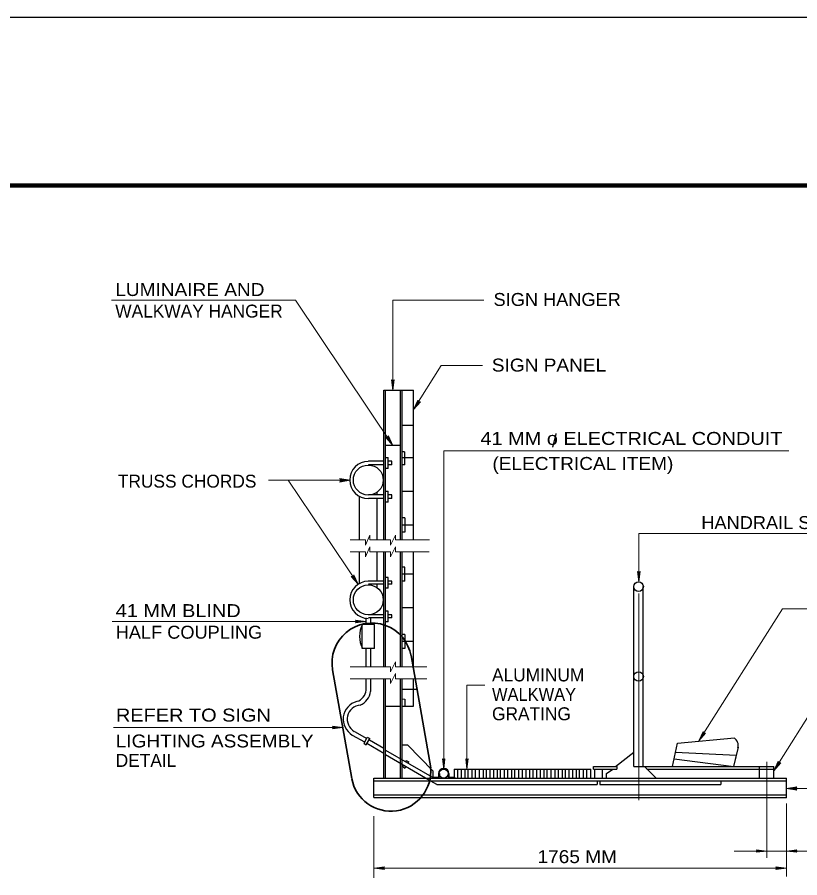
# Model space of a CAD drawing. Extents: x 312601.858 to 312602.699, y 144420.109 to 144420.704.
# Drawn here: x 312602.1557 to 312602.337, y 144420.5041 to 144420.7035 of the extents above; entities that cross this region are included whole.
import ezdxf
from ezdxf.enums import TextEntityAlignment as Align

# ---------------------------------------------------------------- set-up
doc = ezdxf.new("R2010")
doc.units = 0
doc.header["$LTSCALE"] = 0.0012
for name, pattern in [('DOT_DASHED', [7.7, 5, -1.2, 0.3, -1.2]), ('LONG_DASH_SHORT_DASH', [9.9, 6, -1.2, 1.5, -1.2]), ('LONG_DASHED', [7.5, 6, -1.5])]:
    doc.linetypes.add(name, pattern=pattern)
for name, color, linetype, lineweight in [('1', 7, 'Continuous', 25), ('2', 7, 'Continuous', 25), ('39', 7, 'Continuous', 13)]:
    doc.layers.add(name, color=color, linetype=linetype, lineweight=lineweight)

msp = doc.modelspace()

# ---------------------------------------------------------------- hatches: boundary and pattern name
at = {"layer": '39'}
for points in [[(312602.2427, 144420.6193), (312602.243, 144420.6195), (312602.2427, 144420.6171), (312602.2424, 144420.6195)], [(312602.2487, 144420.6144), (312602.2491, 144420.6144), (312602.2475, 144420.6126), (312602.2485, 144420.6148)], [(312602.2415, 144420.6061), (312602.2417, 144420.6065), (312602.2427, 144420.6043), (312602.2411, 144420.6061)], [(312602.2306, 144420.5962), (312602.2304, 144420.5966), (312602.2328, 144420.5962), (312602.2304, 144420.5958)], [(312602.2306, 144420.5962), (312602.2304, 144420.5966), (312602.2328, 144420.5962), (312602.2304, 144420.5958)], [(312602.2997, 144420.5749), (312602.3, 144420.5751), (312602.2997, 144420.5727), (312602.2994, 144420.5751)], [(312602.2997, 144420.5749), (312602.3, 144420.5751), (312602.2997, 144420.5727), (312602.2994, 144420.5751)], [(312602.2335, 144420.5739), (312602.2337, 144420.5743), (312602.2347, 144420.5721), (312602.2331, 144420.5739)], [(312602.2343, 144420.5635), (312602.2341, 144420.5638), (312602.2365, 144420.5635), (312602.2341, 144420.5632)], [(312602.2343, 144420.5635), (312602.2341, 144420.5638), (312602.2365, 144420.5635), (312602.2341, 144420.5632)], [(312602.2289, 144420.5389), (312602.2287, 144420.5392), (312602.2311, 144420.5389), (312602.2287, 144420.5386)], [(312602.2289, 144420.5389), (312602.2287, 144420.5392), (312602.2311, 144420.5389), (312602.2287, 144420.5386)], [(312602.3148, 144420.5376), (312602.3152, 144420.5376), (312602.3136, 144420.5358), (312602.3146, 144420.538)], [(312602.2545, 144420.5315), (312602.2548, 144420.5317), (312602.2545, 144420.5293), (312602.2542, 144420.5317)], [(312602.2599, 144420.5315), (312602.2602, 144420.5317), (312602.2599, 144420.5293), (312602.2596, 144420.5317)], [(312602.2599, 144420.5315), (312602.2602, 144420.5317), (312602.2599, 144420.5293), (312602.2596, 144420.5317)], [(312602.3322, 144420.5307), (312602.3326, 144420.5307), (312602.331, 144420.5289), (312602.332, 144420.5311)], [(312602.3322, 144420.5307), (312602.3326, 144420.5307), (312602.331, 144420.5289), (312602.332, 144420.5311)], [(312602.3361, 144420.5248), (312602.3363, 144420.5244), (312602.3339, 144420.5248), (312602.3363, 144420.5252)], [(312602.3361, 144420.5248), (312602.3363, 144420.5244), (312602.3339, 144420.5248), (312602.3363, 144420.5252)], [(312602.3272, 144420.5103), (312602.327, 144420.5106), (312602.3294, 144420.5103), (312602.327, 144420.51)], [(312602.3272, 144420.5103), (312602.327, 144420.5106), (312602.3294, 144420.5103), (312602.327, 144420.51)], [(312602.3361, 144420.5103), (312602.3363, 144420.51), (312602.3339, 144420.5103), (312602.3363, 144420.5106)], [(312602.3361, 144420.5103), (312602.3363, 144420.51), (312602.3339, 144420.5103), (312602.3363, 144420.5106)], [(312602.2406, 144420.5063), (312602.2408, 144420.506), (312602.2384, 144420.5063), (312602.2408, 144420.5066)], [(312602.2406, 144420.5063), (312602.2408, 144420.506), (312602.2384, 144420.5063), (312602.2408, 144420.5066)], [(312602.3317, 144420.5063), (312602.3315, 144420.5066), (312602.3339, 144420.5063), (312602.3315, 144420.506)]]:
    msp.add_hatch(color=256, dxfattribs=at).paths.add_polyline_path(points)

# ---------------------------------------------------------------- linework, layer by layer
at = {"layer": '1', "lineweight": 13}
for p, q in [((312602.2202, 144420.6379), (312602.1775, 144420.6379)), ((312602.2427, 144420.6043), (312602.2202, 144420.6379)), ((312602.2427, 144420.6171), (312602.2427, 144420.6379)), ((312602.2638, 144420.6379), (312602.2427, 144420.6379)), ((312602.2545, 144420.5293), (312602.2545, 144420.603)), ((312602.3345, 144420.603), (312602.2545, 144420.603)), ((312602.2328, 144420.5962), (312602.2139, 144420.5962)), ((312602.2347, 144420.5721), (312602.2185, 144420.5962)), ((312602.2364, 144420.5812), (312602.2374, 144420.5835)), ((312602.2374, 144420.5824), (312602.2374, 144420.5835)), ((312602.2422, 144420.5812), (312602.2433, 144420.5835)), ((312602.2433, 144420.5824), (312602.2433, 144420.5835)), ((312602.2997, 144420.5839), (312602.3587, 144420.5839)), ((312602.2997, 144420.5727), (312602.2997, 144420.5839)), ((312602.2328, 144420.5824), (312602.2364, 144420.5824)), ((312602.2364, 144420.5812), (312602.2364, 144420.5824)), ((312602.2364, 144420.5785), (312602.2374, 144420.5808)), ((312602.2374, 144420.5796), (312602.2374, 144420.5808)), ((312602.2422, 144420.5812), (312602.2422, 144420.5824)), ((312602.2422, 144420.5785), (312602.2433, 144420.5808)), ((312602.2433, 144420.5824), (312602.2512, 144420.5824)), ((312602.2433, 144420.5796), (312602.2433, 144420.5808)), ((312602.2328, 144420.5796), (312602.2364, 144420.5796)), ((312602.2364, 144420.5785), (312602.2364, 144420.5796)), ((312602.2374, 144420.5796), (312602.2422, 144420.5796)), ((312602.2422, 144420.5785), (312602.2422, 144420.5796)), ((312602.2433, 144420.5796), (312602.2511, 144420.5796)), ((312602.3136, 144420.5358), (312602.333, 144420.5664)), ((312602.333, 144420.5664), (312602.3868, 144420.5664)), ((312602.2365, 144420.5635), (312602.1777, 144420.5635)), ((312602.2422, 144420.5518), (312602.2433, 144420.5541)), ((312602.2422, 144420.5518), (312602.2422, 144420.553)), ((312602.2433, 144420.553), (312602.2433, 144420.5541)), ((312602.2433, 144420.553), (312602.2506, 144420.553)), ((312602.2422, 144420.5491), (312602.2433, 144420.5514)), ((312602.2433, 144420.5502), (312602.2433, 144420.5514)), ((312602.2328, 144420.5502), (312602.2422, 144420.5502)), ((312602.2422, 144420.5491), (312602.2422, 144420.5502)), ((312602.2433, 144420.5502), (312602.2506, 144420.5502)), ((312602.2599, 144420.5293), (312602.2599, 144420.5487)), ((312602.264, 144420.5487), (312602.2599, 144420.5487)), ((312602.2449, 144420.5455), (312602.2455, 144420.5455)), ((312602.331, 144420.5289), (312602.3414, 144420.5454)), ((312602.2311, 144420.5389), (312602.178, 144420.5389)), ((312602.3339, 144420.5248), (312602.3843, 144420.5248)), ((312602.3294, 144420.5087), (312602.3294, 144420.5221)), ((312602.3339, 144420.5044), (312602.3339, 144420.5213)), ((312602.2384, 144420.5063), (312602.3339, 144420.5063))]:
    msp.add_line(p, q, dxfattribs=at)
at = {"layer": '1'}
for p, q in [((312602.2406, 144420.6171), (312602.2449, 144420.6171)), ((312602.2406, 144420.5824), (312602.2406, 144420.6171)), ((312602.241, 144420.5824), (312602.241, 144420.6171)), ((312602.2445, 144420.5824), (312602.2445, 144420.6171)), ((312602.2449, 144420.5824), (312602.2449, 144420.6171)), ((312602.2449, 144420.6171), (312602.2475, 144420.6171)), ((312602.2475, 144420.5824), (312602.2475, 144420.6171)), ((312602.2449, 144420.609), (312602.2475, 144420.609)), ((312602.2445, 144420.6043), (312602.241, 144420.6043)), ((312602.2454, 144420.6028), (312602.2449, 144420.6028)), ((312602.2455, 144420.5998), (312602.2455, 144420.6028)), ((312602.2406, 144420.6006), (312602.2371, 144420.6006)), ((312602.241, 144420.6015), (312602.2416, 144420.6015)), ((312602.2416, 144420.5989), (312602.2416, 144420.6015)), ((312602.2449, 144420.6015), (312602.2475, 144420.6015)), ((312602.2406, 144420.5998), (312602.2371, 144420.5998)), ((312602.2416, 144420.5989), (312602.241, 144420.5989)), ((312602.2425, 144420.5998), (312602.2416, 144420.5998)), ((312602.2455, 144420.5998), (312602.2449, 144420.5998)), ((312602.2406, 144420.5928), (312602.2371, 144420.5928)), ((312602.2391, 144420.5928), (312602.2391, 144420.5935)), ((312602.241, 144420.5937), (312602.2416, 144420.5937)), ((312602.2416, 144420.5911), (312602.2416, 144420.5937)), ((312602.2425, 144420.5928), (312602.2416, 144420.5928)), ((312602.2425, 144420.592), (312602.2425, 144420.5928)), ((312602.2449, 144420.5937), (312602.2475, 144420.5937)), ((312602.235, 144420.5824), (312602.235, 144420.5925)), ((312602.2406, 144420.592), (312602.2371, 144420.592)), ((312602.2391, 144420.5824), (312602.2391, 144420.592)), ((312602.2416, 144420.5911), (312602.241, 144420.5911)), ((312602.2425, 144420.592), (312602.2416, 144420.592)), ((312602.2455, 144420.5875), (312602.2449, 144420.5875)), ((312602.2455, 144420.5875), (312602.2455, 144420.5842)), ((312602.2449, 144420.5859), (312602.2475, 144420.5859)), ((312602.2455, 144420.5842), (312602.2449, 144420.5842)), ((312602.235, 144420.5723), (312602.235, 144420.5796)), ((312602.2391, 144420.5728), (312602.2391, 144420.5796)), ((312602.2406, 144420.553), (312602.2406, 144420.5796)), ((312602.241, 144420.553), (312602.241, 144420.5796)), ((312602.2445, 144420.553), (312602.2445, 144420.5796)), ((312602.2449, 144420.553), (312602.2449, 144420.5796)), ((312602.2475, 144420.553), (312602.2475, 144420.5796)), ((312602.2455, 144420.5761), (312602.2449, 144420.5761)), ((312602.2455, 144420.5728), (312602.2455, 144420.5761)), ((312602.2406, 144420.5728), (312602.2371, 144420.5728)), ((312602.2425, 144420.5728), (312602.2416, 144420.5728)), ((312602.2425, 144420.5721), (312602.2425, 144420.5728)), ((312602.2449, 144420.5745), (312602.2475, 144420.5745)), ((312602.2455, 144420.5728), (312602.2449, 144420.5728)), ((312602.2406, 144420.5721), (312602.2371, 144420.5721)), ((312602.2391, 144420.5713), (312602.2391, 144420.5721)), ((312602.2416, 144420.5712), (312602.241, 144420.5712)), ((312602.2425, 144420.5721), (312602.2416, 144420.5721)), ((312602.2986, 144420.5299), (312602.2986, 144420.5716)), ((312602.3007, 144420.5299), (312602.3007, 144420.5716)), ((312602.2449, 144420.5667), (312602.2475, 144420.5667)), ((312602.2406, 144420.565), (312602.2371, 144420.565)), ((312602.2416, 144420.5659), (312602.241, 144420.5659)), ((312602.2416, 144420.5634), (312602.2416, 144420.5659)), ((312602.2425, 144420.565), (312602.2416, 144420.565)), ((312602.2425, 144420.5643), (312602.2425, 144420.565)), ((312602.2385, 144420.5628), (312602.2356, 144420.5628)), ((312602.2356, 144420.5572), (312602.2356, 144420.5628)), ((312602.2365, 144420.5628), (312602.2365, 144420.5643)), ((312602.2406, 144420.5643), (312602.2371, 144420.5643)), ((312602.2376, 144420.5628), (312602.2376, 144420.5643)), ((312602.2385, 144420.5572), (312602.2385, 144420.5628)), ((312602.2416, 144420.5634), (312602.241, 144420.5634)), ((312602.2425, 144420.5643), (312602.2416, 144420.5643)), ((312602.2455, 144420.5605), (312602.2449, 144420.5605)), ((312602.2449, 144420.5589), (312602.2475, 144420.5589)), ((312602.2455, 144420.5605), (312602.2455, 144420.5572)), ((312602.2385, 144420.5572), (312602.2356, 144420.5572)), ((312602.2365, 144420.553), (312602.2365, 144420.5572)), ((312602.2376, 144420.553), (312602.2376, 144420.5572)), ((312602.2455, 144420.5572), (312602.2449, 144420.5572)), ((312602.2365, 144420.5476), (312602.2365, 144420.5502)), ((312602.2376, 144420.5473), (312602.2376, 144420.5502)), ((312602.2406, 144420.5436), (312602.2406, 144420.5502)), ((312602.241, 144420.5272), (312602.241, 144420.5502)), ((312602.2445, 144420.5272), (312602.2445, 144420.5502)), ((312602.2449, 144420.5272), (312602.2449, 144420.5502)), ((312602.2475, 144420.5439), (312602.2475, 144420.5502)), ((312602.2455, 144420.5455), (312602.2455, 144420.5439)), ((312602.2406, 144420.5272), (312602.2406, 144420.5436)), ((312602.2449, 144420.5439), (312602.2475, 144420.5439)), ((312602.2362, 144420.5355), (312602.2334, 144420.5371)), ((312602.2338, 144420.538), (312602.2367, 144420.5364)), ((312602.2361, 144420.5352), (312602.2365, 144420.5349)), ((312602.2365, 144420.5349), (312602.2374, 144420.5364)), ((312602.2406, 144420.5329), (312602.2367, 144420.5352)), ((312602.2373, 144420.5361), (312602.2406, 144420.5341)), ((312602.3075, 144420.5299), (312602.3087, 144420.5353)), ((312602.3087, 144420.5353), (312602.3219, 144420.5365)), ((312602.2943, 144420.5299), (312602.2986, 144420.5332)), ((312602.3082, 144420.5332), (312602.3223, 144420.5325)), ((312602.3217, 144420.5299), (312602.3228, 144420.5344)), ((312602.3217, 144420.5299), (312602.3225, 144420.5331)), ((312602.2457, 144420.531), (312602.2458, 144420.5313)), ((312602.2458, 144420.5313), (312602.2464, 144420.531)), ((312602.2463, 144420.5307), (312602.2464, 144420.531)), ((312602.3079, 144420.5317), (312602.3217, 144420.5299)), ((312602.2451, 144420.5298), (312602.2452, 144420.5302)), ((312602.2451, 144420.5298), (312602.2455, 144420.5295)), ((312602.2455, 144420.5295), (312602.2458, 144420.5299)), ((312602.252, 144420.5289), (312602.252, 144420.5272)), ((312602.2569, 144420.5293), (312602.2886, 144420.5293)), ((312602.2569, 144420.5293), (312602.2569, 144420.5272)), ((312602.2578, 144420.5272), (312602.2578, 144420.5293)), ((312602.2586, 144420.5272), (312602.2586, 144420.5293)), ((312602.2595, 144420.5272), (312602.2595, 144420.5293)), ((312602.2602, 144420.5272), (312602.2602, 144420.5293)), ((312602.2611, 144420.5272), (312602.2611, 144420.5293)), ((312602.2619, 144420.5272), (312602.2619, 144420.5293)), ((312602.2628, 144420.5272), (312602.2628, 144420.5293)), ((312602.2637, 144420.5272), (312602.2637, 144420.5293)), ((312602.2644, 144420.5272), (312602.2644, 144420.5293)), ((312602.2653, 144420.5272), (312602.2653, 144420.5293)), ((312602.2661, 144420.5272), (312602.2661, 144420.5293)), ((312602.267, 144420.5272), (312602.267, 144420.5293)), ((312602.2677, 144420.5272), (312602.2677, 144420.5293)), ((312602.2686, 144420.5272), (312602.2686, 144420.5293)), ((312602.2694, 144420.5272), (312602.2694, 144420.5293)), ((312602.2703, 144420.5272), (312602.2703, 144420.5293)), ((312602.271, 144420.5272), (312602.271, 144420.5293)), ((312602.2719, 144420.5272), (312602.2719, 144420.5293)), ((312602.2728, 144420.5272), (312602.2728, 144420.5293)), ((312602.2736, 144420.5272), (312602.2736, 144420.5293)), ((312602.2745, 144420.5272), (312602.2745, 144420.5293)), ((312602.2752, 144420.5272), (312602.2752, 144420.5293)), ((312602.2761, 144420.5272), (312602.2761, 144420.5293)), ((312602.2769, 144420.5272), (312602.2769, 144420.5293)), ((312602.2778, 144420.5272), (312602.2778, 144420.5293)), ((312602.2785, 144420.5272), (312602.2785, 144420.5293)), ((312602.2794, 144420.5272), (312602.2794, 144420.5293)), ((312602.2803, 144420.5272), (312602.2803, 144420.5293)), ((312602.2811, 144420.5272), (312602.2811, 144420.5293)), ((312602.282, 144420.5272), (312602.282, 144420.5293)), ((312602.2827, 144420.5272), (312602.2827, 144420.5293)), ((312602.2836, 144420.5272), (312602.2836, 144420.5293)), ((312602.2844, 144420.5272), (312602.2844, 144420.5293)), ((312602.2853, 144420.5272), (312602.2853, 144420.5293)), ((312602.286, 144420.5272), (312602.286, 144420.5293)), ((312602.2869, 144420.5272), (312602.2869, 144420.5293)), ((312602.2877, 144420.5272), (312602.2877, 144420.5293)), ((312602.2886, 144420.5272), (312602.2886, 144420.5293)), ((312602.2892, 144420.5293), (312602.2892, 144420.5299)), ((312602.2892, 144420.5299), (312602.2946, 144420.5299)), ((312602.2892, 144420.5293), (312602.2946, 144420.5293)), ((312602.2895, 144420.5272), (312602.2895, 144420.5293)), ((312602.2913, 144420.5272), (312602.2913, 144420.5293)), ((312602.2922, 144420.5283), (312602.2937, 144420.5293)), ((312602.2946, 144420.5299), (312602.2946, 144420.5293)), ((312602.2986, 144420.5299), (312602.331, 144420.5299)), ((312602.301, 144420.5299), (312602.3037, 144420.5272)), ((312602.3016, 144420.5293), (312602.331, 144420.5293)), ((312602.3277, 144420.5272), (312602.3277, 144420.5299)), ((312602.331, 144420.5272), (312602.331, 144420.5299)), ((312602.2383, 144420.5227), (312602.2383, 144420.5272)), ((312602.2529, 144420.5257), (312602.2503, 144420.5272)), ((312602.252, 144420.5274), (312602.2532, 144420.5274)), ((312602.2533, 144420.5283), (312602.2533, 144420.5275)), ((312602.2535, 144420.5283), (312602.2535, 144420.5274)), ((312602.2556, 144420.5283), (312602.2556, 144420.5274)), ((312602.2556, 144420.5272), (312602.3339, 144420.5272)), ((312602.2922, 144420.5272), (312602.2922, 144420.5283)), ((312602.3339, 144420.5226), (312602.3339, 144420.5272)), ((312602.2383, 144420.5266), (312602.3339, 144420.5266)), ((312602.2383, 144420.5233), (312602.3339, 144420.5233)), ((312602.2383, 144420.5227), (312602.3339, 144420.5227))]:
    msp.add_line(p, q, dxfattribs=at)
at = {"layer": '1', "linetype": 'LONG_DASH_SHORT_DASH', "lineweight": 13}
msp.add_line((312602.2997, 144420.5221), (312602.2997, 144420.57), dxfattribs=at)
at = {"layer": '1', "lineweight": 35}
for p, q in [((312602.2515, 144420.5296), (312602.247, 144420.5556)), ((312602.2332, 144420.5271), (312602.2287, 144420.5523))]:
    msp.add_line(p, q, dxfattribs=at)
at = {"layer": '1', "linetype": 'LONG_DASHED'}
for p, q in [((312602.2448, 144420.5478), (312602.2482, 144420.5478)), ((312602.241, 144420.5439), (312602.2445, 144420.5439)), ((312602.241, 144420.5337), (312602.2523, 144420.5272)), ((312602.2503, 144420.5272), (312602.241, 144420.5326)), ((312602.2529, 144420.5257), (312602.2901, 144420.5257)), ((312602.2901, 144420.5266), (312602.2901, 144420.5257)), ((312602.2907, 144420.5266), (312602.2907, 144420.5257)), ((312602.2907, 144420.5257), (312602.3187, 144420.5257)), ((312602.3187, 144420.5266), (312602.3187, 144420.5257))]:
    msp.add_line(p, q, dxfattribs=at)
at = {"layer": '1', "linetype": 'DOT_DASHED', "lineweight": 13}
for p, q in [((312602.3294, 144420.5214), (312602.3294, 144420.531)), ((312602.3294, 144420.5144), (312602.3294, 144420.5277))]:
    msp.add_line(p, q, dxfattribs=at)
at = {"layer": '1', "lineweight": 13}
for points in [[(312602.2475, 144420.6126), (312602.2539, 144420.6228), (312602.2635, 144420.6228)], [(312602.2374, 144420.5824), (312602.239, 144420.5824), (312602.2422, 144420.5824)], [(312602.2328, 144420.553), (312602.2365, 144420.553), (312602.2422, 144420.553)], [(312602.3218, 144420.5103), (312602.3339, 144420.5103), (312602.3514, 144420.5103)]]:
    msp.add_lwpolyline(points, dxfattribs=at)
at = {"layer": '1'}
for points in [[(312602.2425, 144420.5998), (312602.2425, 144420.6006), (312602.2416, 144420.6006)], [(312602.2416, 144420.5712), (312602.2416, 144420.5737), (312602.241, 144420.5737)], [(312602.2361, 144420.5352), (312602.2368, 144420.5367), (312602.2374, 144420.5364)], [(312602.2449, 144420.5349), (312602.2461, 144420.5349), (312602.252, 144420.5289)], [(312602.2383, 144420.5272), (312602.2533, 144420.5272), (312602.2557, 144420.5272)], [(312602.2557, 144420.5283), (312602.2557, 144420.5275), (312602.2578, 144420.5272)], [(312602.2559, 144420.5274), (312602.2568, 144420.5274), (312602.2568, 144420.5272)]]:
    msp.add_lwpolyline(points, dxfattribs=at)
for centre, radius in [((312602.237038, 144420.596261), 0.003469), ((312602.299656, 144420.57156), 0.00111), ((312602.237038, 144420.568507), 0.003469), ((312602.299656, 144420.550745), 0.00111), ((312602.2545, 144420.52825), 0.00105)]:
    msp.add_circle(centre, radius, dxfattribs=at)
for centre, radius, start, end in [((312602.237038, 144420.596261), 0.004302, 90, 270), ((312602.237038, 144420.568507), 0.004302, 90, 270), ((312602.241184, 144420.560042), 0.006191, 153.36603, 206.63397), ((312602.23365, 144420.54775), 0.002854, 284.62088, 356.98721), ((312602.23365, 144420.54775), 0.003926, 292.82281, 353.41806), ((312602.23545, 144420.54085), 0.004243, 104.62087, 239.93142), ((312602.23545, 144420.54085), 0.003293, 94.82891, 239.50477), ((312602.3205, 144420.5347), 0.002255, 346.86598, 54.41791), ((312602.2545, 144420.52825), 0.0012, 0, 180), ((312602.25315, 144420.5275), 0.00015, 270, 0), ((312602.25327, 144420.52738), 0.00018, 270, 0), ((312602.25573, 144420.52738), 0.00018, 180, 270), ((312602.25585, 144420.5275), 0.00015, 180, 270)]:
    msp.add_arc(centre, radius, start, end, dxfattribs=at)
at = {"layer": '1', "lineweight": 35}
for centre, start, end in [((312602.23785, 144420.5539), 9.83785, 190.19851), ((312602.242275, 144420.528775), 190.76254, 5.58634)]:
    msp.add_arc(centre, 0.009237, start, end, dxfattribs=at)
at = {"layer": '1', "lineweight": 13}
for points in [[(312602.2383, 144420.5066), (312602.2383, 144420.5184)], [(312602.2383, 144420.5041), (312602.2383, 144420.518)]]:
    msp.add_open_spline(points, degree=1, dxfattribs=at)
at = {"layer": '39', "lineweight": 25}
msp.add_line((312601.8578, 144420.7035), (312602.6988, 144420.7035), dxfattribs=at)
at = {"layer": '39', "lineweight": 158}
msp.add_line((312601.9088, 144420.6645), (312602.6838, 144420.6645), dxfattribs=at)
at = {"layer": '39'}
for points in [[(312602.2427, 144420.6193), (312602.243, 144420.6195), (312602.2427, 144420.6171), (312602.2424, 144420.6195)], [(312602.2487, 144420.6144), (312602.2491, 144420.6144), (312602.2475, 144420.6126), (312602.2485, 144420.6148)], [(312602.2415, 144420.6061), (312602.2417, 144420.6065), (312602.2427, 144420.6043), (312602.2411, 144420.6061)], [(312602.2306, 144420.5962), (312602.2304, 144420.5966), (312602.2328, 144420.5962), (312602.2304, 144420.5958)], [(312602.2306, 144420.5962), (312602.2304, 144420.5966), (312602.2328, 144420.5962), (312602.2304, 144420.5958)], [(312602.2997, 144420.5749), (312602.3, 144420.5751), (312602.2997, 144420.5727), (312602.2994, 144420.5751)], [(312602.2997, 144420.5749), (312602.3, 144420.5751), (312602.2997, 144420.5727), (312602.2994, 144420.5751)], [(312602.2335, 144420.5739), (312602.2337, 144420.5743), (312602.2347, 144420.5721), (312602.2331, 144420.5739)], [(312602.2343, 144420.5635), (312602.2341, 144420.5638), (312602.2365, 144420.5635), (312602.2341, 144420.5632)], [(312602.2343, 144420.5635), (312602.2341, 144420.5638), (312602.2365, 144420.5635), (312602.2341, 144420.5632)], [(312602.2289, 144420.5389), (312602.2287, 144420.5392), (312602.2311, 144420.5389), (312602.2287, 144420.5386)], [(312602.2289, 144420.5389), (312602.2287, 144420.5392), (312602.2311, 144420.5389), (312602.2287, 144420.5386)], [(312602.3148, 144420.5376), (312602.3152, 144420.5376), (312602.3136, 144420.5358), (312602.3146, 144420.538)], [(312602.2545, 144420.5315), (312602.2548, 144420.5317), (312602.2545, 144420.5293), (312602.2542, 144420.5317)], [(312602.2599, 144420.5315), (312602.2602, 144420.5317), (312602.2599, 144420.5293), (312602.2596, 144420.5317)], [(312602.2599, 144420.5315), (312602.2602, 144420.5317), (312602.2599, 144420.5293), (312602.2596, 144420.5317)], [(312602.3322, 144420.5307), (312602.3326, 144420.5307), (312602.331, 144420.5289), (312602.332, 144420.5311)], [(312602.3322, 144420.5307), (312602.3326, 144420.5307), (312602.331, 144420.5289), (312602.332, 144420.5311)], [(312602.3361, 144420.5248), (312602.3363, 144420.5244), (312602.3339, 144420.5248), (312602.3363, 144420.5252)], [(312602.3361, 144420.5248), (312602.3363, 144420.5244), (312602.3339, 144420.5248), (312602.3363, 144420.5252)], [(312602.3272, 144420.5103), (312602.327, 144420.5106), (312602.3294, 144420.5103), (312602.327, 144420.51)], [(312602.3272, 144420.5103), (312602.327, 144420.5106), (312602.3294, 144420.5103), (312602.327, 144420.51)], [(312602.3361, 144420.5103), (312602.3363, 144420.51), (312602.3339, 144420.5103), (312602.3363, 144420.5106)], [(312602.3361, 144420.5103), (312602.3363, 144420.51), (312602.3339, 144420.5103), (312602.3363, 144420.5106)], [(312602.2406, 144420.5063), (312602.2408, 144420.506), (312602.2384, 144420.5063), (312602.2408, 144420.5066)], [(312602.2406, 144420.5063), (312602.2408, 144420.506), (312602.2384, 144420.5063), (312602.2408, 144420.5066)], [(312602.3317, 144420.5063), (312602.3315, 144420.5066), (312602.3339, 144420.5063), (312602.3315, 144420.506)]]:
    msp.add_lwpolyline(points, close=True, dxfattribs=at)

# ---------------------------------------------------------------- texts
at = {"layer": '1'}
for s, width, p in [('LUMINAIRE AND', 1.1, (312602.1784, 144420.6389)), ('(ELECTRICAL ITEM)', 1.1, (312602.2658, 144420.5986)), ('WALKWAY', 0.95, (312602.2657, 144420.5451)), ('LIGHTING ASSEMBLY', 1.1, (312602.1785, 144420.5343))]:
    msp.add_text(s, height=0.003, dxfattribs=dict(at, width=width)).set_placement(p)
for s, width, p in [('SIGN HANGER', 1.05, (312602.2808, 144420.6366)), ('SIGN PANEL', 1.1, (312602.2789, 144420.6214)), ('41 MM o ELECTRICAL CONDUIT', 1.15, (312602.298, 144420.6044)), ('REFER TO SIGN', 1.15, (312602.1965, 144420.5403))]:
    msp.add_text(s, height=0.003, dxfattribs=dict(at, width=width)).set_placement(p, align=Align.CENTER)
for s, p in [('WALKWAY HANGER', (312602.1784, 144420.6339)), ('ALUMINUM', (312602.2657, 144420.5496)), ('GRATING', (312602.2657, 144420.5406)), ('DETAIL', (312602.1785, 144420.5298))]:
    msp.add_text(s, height=0.003, dxfattribs=at).set_placement(p)
msp.add_text('TRUSS CHORDS', height=0.003, dxfattribs=at).set_placement((312602.19505, 144420.5945), align=Align.CENTER)
at = {"layer": '2'}
msp.add_text('/', height=0.003, dxfattribs=at).set_placement((312602.28015, 144420.6039), align=Align.CENTER)
for s, width, p in [('HANDRAIL SUPPORT', 1.05, (312602.3142, 144420.5849)), ('41 MM BLIND', 1.15, (312602.1785, 144420.5645)), ('HALF COUPLING', 1.05, (312602.1785, 144420.5595))]:
    msp.add_text(s, height=0.003, dxfattribs=dict(at, width=width)).set_placement(p)
at = {"layer": '2', "width": 1.1}
msp.add_text('1765 MM', height=0.003, dxfattribs=at).set_placement((312602.28545, 144420.5075), align=Align.CENTER)

doc.saveas('drawing.dxf')
